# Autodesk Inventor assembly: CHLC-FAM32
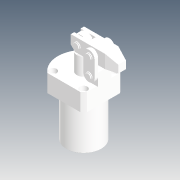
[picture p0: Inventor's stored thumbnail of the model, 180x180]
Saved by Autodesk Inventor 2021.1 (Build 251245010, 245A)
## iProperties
Created: 2019-04
Part Number: CHLC-FAM32
Description: STEP AP214
Document SubType Name: Assembly
Designer: user
Title: CHLC-FAM32.STEP
Revision Number: ÈÎºÎ
Sending System: SolidWorks 2016
Preprocessor: SwSTEP 2.0
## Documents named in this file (10)
- D:\Vault_2016\Projekty\Clamptek\Hydraulic\CHLC\CHLC-32\Inventor\CHLC-FAM32\CHLC-FAM32.iam
- D:\Vault_2016\Projekty\Clamptek\Hydraulic\CHLC\CHLC-32\Inventor\CHLC-FAM32\CHLC-FAM32-05_1.ipt
- D:\Vault_2016\Projekty\Clamptek\Hydraulic\CHLC\CHLC-32\Inventor\CHLC-FAM32\CHLC-32-03_1.ipt
- D:\Vault_2016\Projekty\Clamptek\Hydraulic\CHLC\CHLC-32\Inventor\CHLC-FAM32\CHLC-32-08_1.ipt
- D:\Vault_2016\Projekty\Clamptek\Hydraulic\CHLC\CHLC-32\Inventor\CHLC-FAM32\CHLC-32-02_1.ipt
- D:\Vault_2016\Projekty\Clamptek\Hydraulic\CHLC\CHLC-32\Inventor\CHLC-FAM32\CHLC-32-04_1_1.ipt
- D:\Vault_2016\Projekty\Clamptek\Hydraulic\CHLC\CHLC-32\Inventor\CHLC-FAM32\LHC01D-32-01_1.ipt
- D:\Vault_2016\Projekty\Clamptek\Hydraulic\CHLC\CHLC-32\Inventor\CHLC-FAM32\M6LS_1.ipt
- D:\Vault_2016\Projekty\Clamptek\Hydraulic\CHLC\CHLC-32\Inventor\CHLC-FAM32\socket set screw flat point_iso_ISO 4026 - M5 x 6-N.ipt
- D:\Vault_2016\Projekty\Clamptek\Hydraulic\CHLC\CHLC-32\Inventor\CHLC-FAM32\Ñ¹±Û.ipt
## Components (18 placed, 18 different names)
1. CHLC-FAM32-05_1_1
2. CHLC-32-03_1_2
3. CHLC-32-03_1_3
4. CHLC-32-08_1_4
5. CHLC-32-02_1_5
6. CHLC-32-04_1_1_6
7. CHLC-32-04_1_1_7
8. LHC01D-32-01_1_8
9. LHC01D-32-01_1_9
10. LHC01D-32-01_1_10
11. LHC01D-32-01_1_11
12. LHC01D-32-01_1_12
13. LHC01D-32-01_1_13
14. M6LS_1_14
15. M6LS_1_15
16. socket set screw flat point_iso_ISO 4026 - M5 x 6-N_16
17. socket set screw flat point_iso_ISO 4026 - M5 x 6-N_17
18. Ñ¹±Û_18
